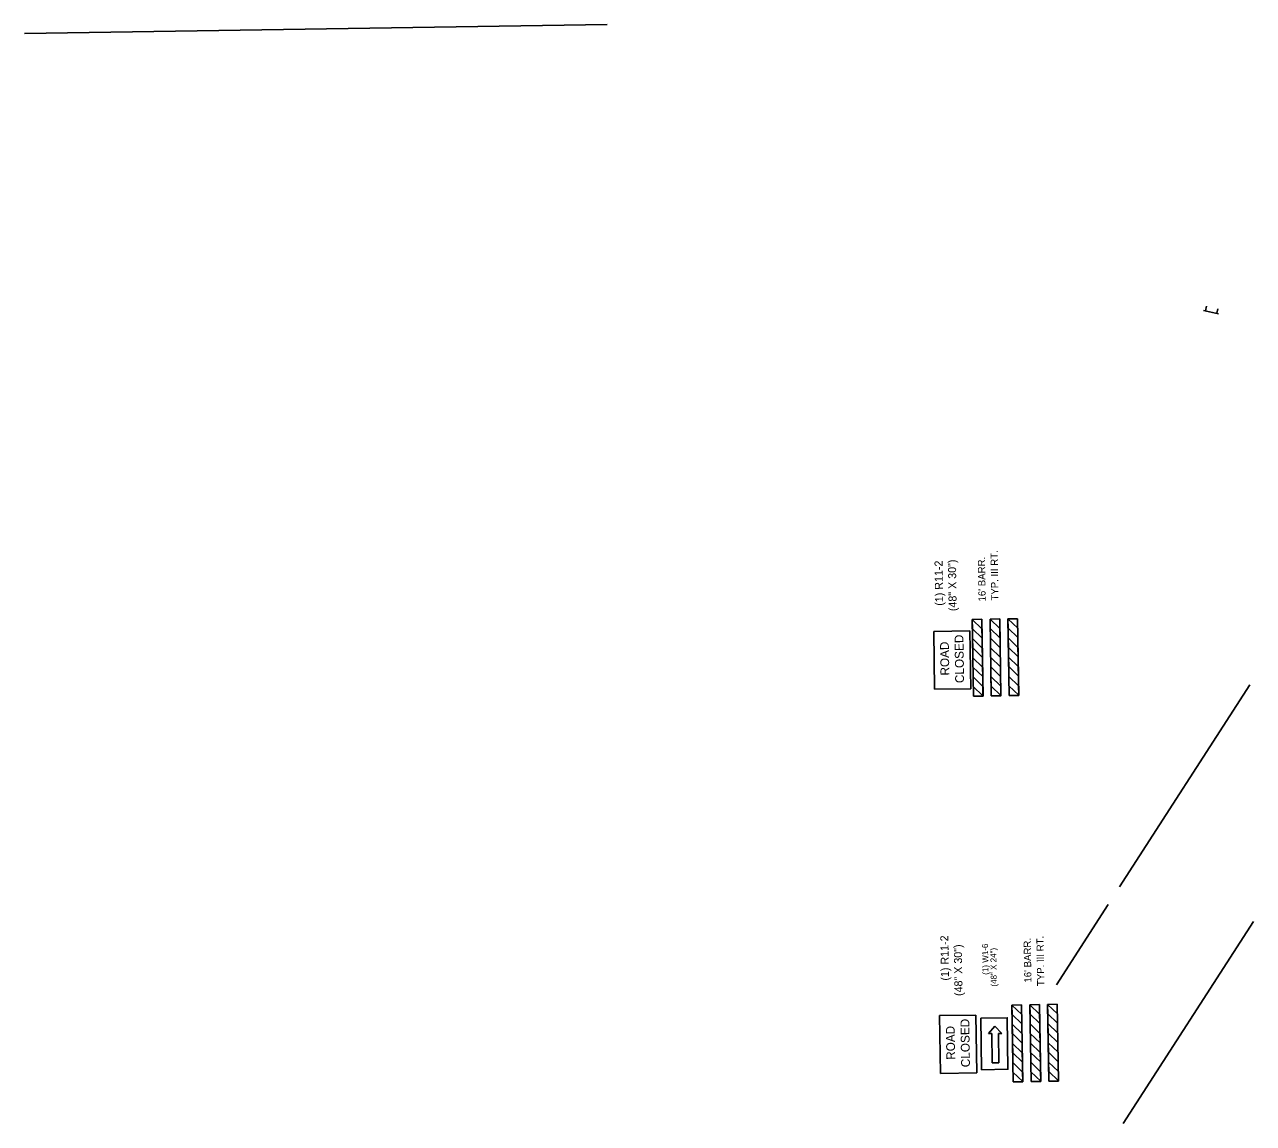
# Model space of a CAD drawing. Extents: x 1770018 to 1773492, y 718230 to 729141.
# Drawn here: x 1772262 to 1773492, y 719320 to 720419 of the extents above; entities that cross this region are included whole.
import ezdxf

# ---------------------------------------------------------------- set-up
doc = ezdxf.new("R2010")
doc.units = 0
doc.layers.add('R_Border PE', color=7, linetype='Continuous')
doc.layers.add('R_MOT', color=7, linetype='Continuous')

msp = doc.modelspace()

# ---------------------------------------------------------------- linework, layer by layer
at = {"layer": 'R_Border PE'}
for p, q in [((1773357.7, 719556.2), (1773488, 719758.4)), ((1773294.5, 719458.2), (1773346.4, 719538.7)), ((1773361.4, 719319.5), (1773491.6, 719521.6))]:
    msp.add_line(p, q, dxfattribs=at)
at = {"layer": 'R_MOT'}
for p, q in [((1772845.3, 720419.1), (1772262.3, 720410.1)), ((1773443.7, 720132.7), (1773444.7, 720137.3)), ((1773456.8, 720129.7), (1773441.6, 720133.1)), ((1773454.9, 720130.2), (1773455.9, 720134.8)), ((1773220, 719824.1), (1773210.3, 719823.9)), ((1773211.5, 719747), (1773210.3, 719823.9)), ((1773220, 719824), (1773219.9, 719824.1)), ((1773221.2, 719747.2), (1773220, 719824.1)), ((1773237.8, 719824.3), (1773228.2, 719824.2)), ((1773237.8, 719824.3), (1773228.2, 719824.2)), ((1773229.4, 719747.3), (1773228.2, 719824.2)), ((1773239, 719747.5), (1773237.8, 719824.3)), ((1773255.7, 719824.6), (1773246.1, 719824.5)), ((1773247.2, 719747.6), (1773246.1, 719824.5)), ((1773256.9, 719747.7), (1773255.7, 719824.6)), ((1773208, 719812.4), (1773171.8, 719811.9)), ((1773172.6, 719753.9), (1773171.8, 719811.9)), ((1773208.9, 719754.5), (1773208, 719812.4)), ((1773208.9, 719754.5), (1773172.6, 719753.9)), ((1773221.2, 719747.2), (1773211.5, 719747)), ((1773239, 719747.5), (1773229.4, 719747.3)), ((1773256.9, 719747.7), (1773247.2, 719747.6)), ((1773259.7, 719438.2), (1773250.1, 719438)), ((1773251.3, 719361.1), (1773250.1, 719438)), ((1773259.7, 719438.1), (1773259.7, 719438.2)), ((1773260.9, 719361.3), (1773259.7, 719438.2)), ((1773277.6, 719438.4), (1773268, 719438.3)), ((1773277.6, 719438.4), (1773268, 719438.3)), ((1773269.2, 719361.4), (1773268, 719438.3)), ((1773278.8, 719361.6), (1773277.6, 719438.4)), ((1773295.4, 719438.7), (1773285.8, 719438.6)), ((1773287, 719361.7), (1773285.8, 719438.6)), ((1773296.6, 719361.8), (1773295.4, 719438.7)), ((1773213.9, 719428), (1773177.7, 719427.4)), ((1773178.6, 719369.5), (1773177.7, 719427.4)), ((1773214.8, 719370), (1773213.9, 719428)), ((1773226.7, 719409.4), (1773233.1, 719416.7)), ((1773233.1, 719416.7), (1773239.8, 719409.6)), ((1773229.9, 719409.5), (1773226.7, 719409.4)), ((1773230.4, 719380.1), (1773229.9, 719409.5)), ((1773236.9, 719380.2), (1773236.5, 719409.6)), ((1773236.5, 719409.6), (1773239.8, 719409.6)), ((1773230.4, 719380.1), (1773236.9, 719380.2)), ((1773214.8, 719370), (1773178.6, 719369.5)), ((1773260.9, 719361.3), (1773251.3, 719361.1)), ((1773278.8, 719361.6), (1773269.2, 719361.4)), ((1773296.6, 719361.8), (1773287, 719361.7))]:
    msp.add_line(p, q, dxfattribs=at)
for points in [[(1773210.3, 719823.9), (1773210.5, 719814.5), (1773220.2, 719805), (1773220.1, 719814.4)], [(1773228.2, 719824.2), (1773228.4, 719814.7), (1773238.1, 719805.3), (1773238, 719814.7)], [(1773246.1, 719824.5), (1773246.2, 719815), (1773256, 719805.6), (1773255.8, 719815)], [(1773210.6, 719804.7), (1773210.8, 719795.3), (1773220.5, 719785.8), (1773220.4, 719795.2)], [(1773228.5, 719805), (1773228.7, 719795.5), (1773238.4, 719786.1), (1773238.3, 719795.5)], [(1773246.4, 719805.3), (1773246.5, 719795.8), (1773256.3, 719786.4), (1773256.1, 719795.8)], [(1773210.9, 719785.5), (1773211.1, 719776.1), (1773220.8, 719766.6), (1773220.7, 719776)], [(1773228.8, 719785.8), (1773229, 719776.3), (1773238.7, 719766.9), (1773238.6, 719776.3)], [(1773246.6, 719786.1), (1773246.8, 719776.6), (1773256.6, 719767.2), (1773256.4, 719776.6)], [(1773246.9, 719766.8), (1773247.1, 719757.4), (1773256.9, 719747.9), (1773256.7, 719757.4)], [(1773211.2, 719766.3), (1773211.4, 719756.8), (1773221.1, 719747.4), (1773221, 719756.8)], [(1773229.1, 719766.6), (1773229.3, 719757.1), (1773239, 719747.7), (1773238.9, 719757.1)], [(1773250.1, 719438), (1773250.3, 719428.6), (1773260, 719419.1), (1773259.9, 719428.5)], [(1773268, 719438.3), (1773268.2, 719428.8), (1773277.9, 719419.4), (1773277.7, 719428.8)], [(1773285.8, 719438.6), (1773286, 719429.1), (1773295.7, 719419.7), (1773295.6, 719429.1)], [(1773218.9, 719424.9), (1773219.7, 719373.3), (1773246.1, 719373.7), (1773245.3, 719425.3)], [(1773250.4, 719418.8), (1773250.6, 719409.4), (1773260.3, 719399.9), (1773260.2, 719409.3)], [(1773268.3, 719419.1), (1773268.4, 719409.6), (1773278.2, 719400.2), (1773278, 719409.6)], [(1773286.1, 719419.4), (1773286.3, 719409.9), (1773296, 719400.5), (1773295.9, 719409.9)], [(1773250.7, 719399.6), (1773250.9, 719390.2), (1773260.6, 719380.7), (1773260.4, 719390.1)], [(1773268.6, 719399.9), (1773268.7, 719390.4), (1773278.5, 719381), (1773278.3, 719390.4)], [(1773286.4, 719400.2), (1773286.6, 719390.7), (1773296.3, 719381.3), (1773296.2, 719390.7)], [(1773251, 719380.4), (1773251.1, 719370.9), (1773260.9, 719361.5), (1773260.7, 719370.9)], [(1773268.9, 719380.7), (1773269, 719371.2), (1773278.8, 719361.8), (1773278.6, 719371.2)], [(1773286.7, 719380.9), (1773286.9, 719371.5), (1773296.6, 719362), (1773296.5, 719371.5)]]:
    msp.add_lwpolyline(points, close=True, dxfattribs=at)

# ---------------------------------------------------------------- texts
for s, height, p in [('TYP. III RT.', 7.204, (1773236.6, 719842.8)), ('(1) R11-2', 8, (1773181.3, 719837.6)), ('(48" X 30")', 8.004, (1773194.8, 719832.2)), ("16' BARR.", 7.2, (1773223.8, 719841.9)), ('CLOSED', 8.82, (1773202.2, 719760.2)), ('ROAD', 8.77, (1773187.4, 719767.8)), ('(1) R11-2', 8, (1773187.1, 719462.5)), ('(48" X 30")', 8.004, (1773200.7, 719447.1)), ('(1) W1-6', 6, (1773226.6, 719468.3)), ("16' BARR.", 7.2, (1773269.6, 719460.5)), ('TYP. III RT.', 7.204, (1773282.5, 719457)), ('(48" X 24")', 6, (1773235, 719456.5)), ('CLOSED', 8.82, (1773208.1, 719375.8)), ('ROAD', 8.77, (1773193.3, 719383.3))]:
    msp.add_text(s, height=height, rotation=90.8827, dxfattribs=at).set_placement(p)

doc.saveas('drawing.dxf')
